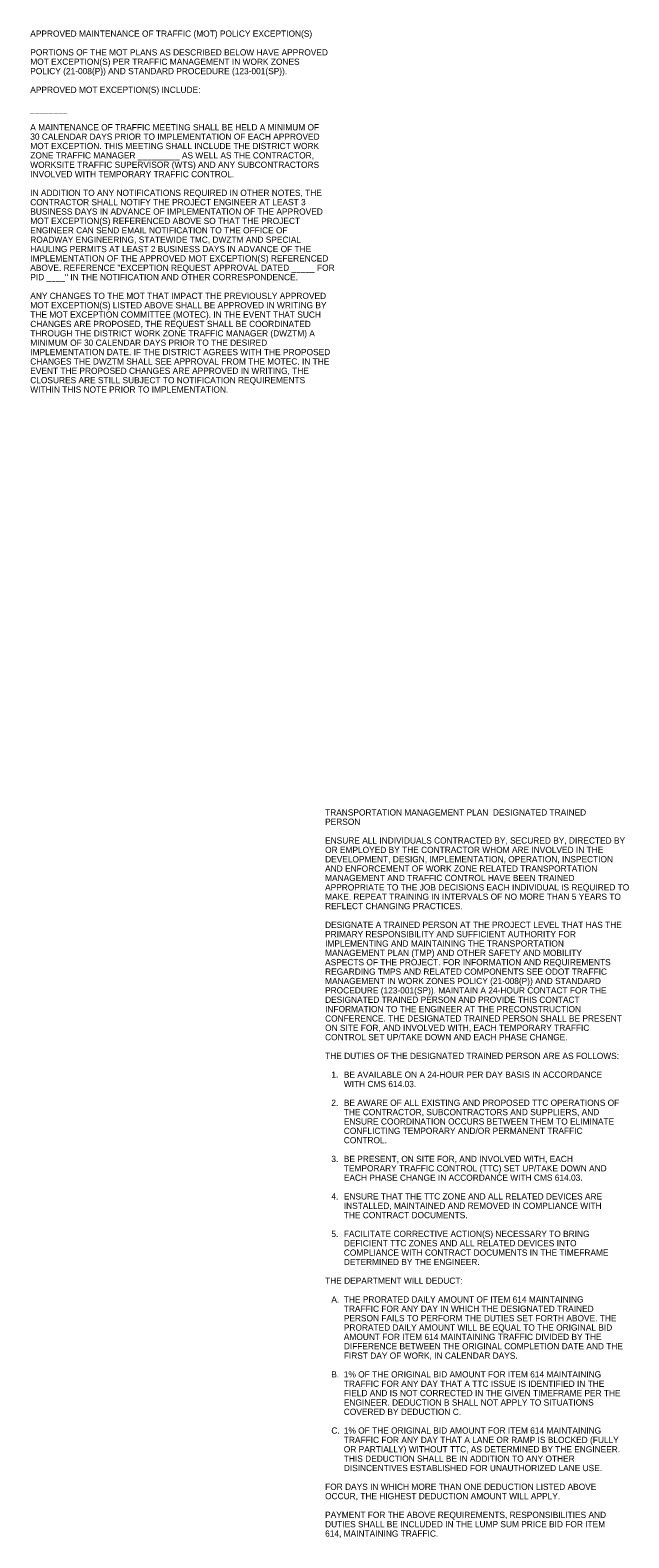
# Model space of a CAD drawing. Extents: x -65.5 to 34, y -24.3 to 23.1.
# Drawn here: x -21.45 to -8.02, y -15.72 to 18.08 of the extents above; entities that cross this region are included whole.
import ezdxf

# ---------------------------------------------------------------- set-up
doc = ezdxf.new("R2010")
doc.units = 0
doc.layers.add('SH_Text', color=7, linetype='Continuous')

msp = doc.modelspace()

# ---------------------------------------------------------------- texts
at = {"layer": 'SH_Text'}
for s, p in [('APPROVED MAINTENANCE OF TRAFFIC (MOT) POLICY EXCEPTION(S)', (-21.449, 17.935)), ('PORTIONS OF THE MOT PLANS AS DESCRIBED BELOW HAVE APPROVED ', (-21.449, 17.515)), ('MOT EXCEPTION(S) PER TRAFFIC MANAGEMENT IN WORK ZONES ', (-21.449, 17.305)), ('POLICY (21-008(P)) AND STANDARD PROCEDURE (123-001(SP)).', (-21.449, 17.095)), ('APPROVED MOT EXCEPTION(S) INCLUDE:', (-21.449, 16.675)), ('________', (-21.449, 16.255)), ('A MAINTENANCE OF TRAFFIC MEETING SHALL BE HELD A MINIMUM OF ', (-21.449, 15.835)), ('30 CALENDAR DAYS PRIOR TO IMPLEMENTATION OF EACH APPROVED ', (-21.449, 15.625)), ('MOT EXCEPTION. THIS MEETING SHALL INCLUDE THE DISTRICT WORK ', (-21.449, 15.415)), ('ZONE TRAFFIC MANAGER _________ AS WELL AS THE CONTRACTOR, ', (-21.449, 15.205)), ('WORKSITE TRAFFIC SUPERVISOR (WTS) AND ANY SUBCONTRACTORS ', (-21.449, 14.995)), ('INVOLVED WITH TEMPORARY TRAFFIC CONTROL.', (-21.449, 14.785)), ('CONTRACTOR SHALL NOTIFY THE PROJECT ENGINEER AT LEAST 3 ', (-21.449, 14.155)), ('IN ADDITION TO ANY NOTIFICATIONS REQUIRED IN OTHER NOTES, THE ', (-21.449, 14.365)), ('BUSINESS DAYS IN ADVANCE OF IMPLEMENTATION OF THE APPROVED ', (-21.449, 13.945)), ('MOT EXCEPTION(S) REFERENCED ABOVE SO THAT THE PROJECT ', (-21.449, 13.735)), ('ENGINEER CAN SEND EMAIL NOTIFICATION TO THE OFFICE OF ', (-21.449, 13.525)), ('ROADWAY ENGINEERING, STATEWIDE TMC, DWZTM AND SPECIAL ', (-21.449, 13.315)), ('HAULING PERMITS AT LEAST 2 BUSINESS DAYS IN ADVANCE OF THE ', (-21.449, 13.105)), ('IMPLEMENTATION OF THE APPROVED MOT EXCEPTION(S) REFERENCED ', (-21.449, 12.895)), ('ABOVE. REFERENCE "EXCEPTION REQUEST APPROVAL DATED _____ FOR ', (-21.449, 12.685)), ('PID ____" IN THE NOTIFICATION AND OTHER CORRESPONDENCE.', (-21.449, 12.475)), ('ANY CHANGES TO THE MOT THAT IMPACT THE PREVIOUSLY APPROVED ', (-21.449, 12.055)), ('MOT EXCEPTION(S) LISTED ABOVE SHALL BE APPROVED IN WRITING BY ', (-21.449, 11.845)), ('THE MOT EXCEPTION COMMITTEE (MOTEC). IN THE EVENT THAT SUCH ', (-21.449, 11.635)), ('CHANGES ARE PROPOSED, THE REQUEST SHALL BE COORDINATED ', (-21.449, 11.425)), ('THROUGH THE DISTRICT WORK ZONE TRAFFIC MANAGER (DWZTM) A ', (-21.449, 11.215)), ('MINIMUM OF 30 CALENDAR DAYS PRIOR TO THE DESIRED ', (-21.449, 11.005)), ('IMPLEMENTATION DATE. IF THE DISTRICT AGREES WITH THE PROPOSED ', (-21.449, 10.795)), ('CHANGES THE DWZTM SHALL SEE APPROVAL FROM THE MOTEC. IN THE ', (-21.449, 10.585)), ('EVENT THE PROPOSED CHANGES ARE APPROVED IN WRITING, THE ', (-21.449, 10.375)), ('CLOSURES ARE STILL SUBJECT TO NOTIFICATION REQUIREMENTS ', (-21.449, 10.165)), ('WITHIN THIS NOTE PRIOR TO IMPLEMENTATION.', (-21.449, 9.955)), ('TRANSPORTATION MANAGEMENT PLAN  DESIGNATED TRAINED ', (-14.834, 0.473)), ('PERSON', (-14.834, 0.263)), ('OR EMPLOYED BY THE CONTRACTOR WHOM ARE INVOLVED IN THE ', (-14.834, -0.367)), ('ENSURE ALL INDIVIDUALS CONTRACTED BY, SECURED BY, DIRECTED BY ', (-14.834, -0.157)), ('AND ENFORCEMENT OF WORK ZONE RELATED TRANSPORTATION ', (-14.834, -0.787)), ('DEVELOPMENT, DESIGN, IMPLEMENTATION, OPERATION, INSPECTION ', (-14.834, -0.577)), ('MANAGEMENT AND TRAFFIC CONTROL HAVE BEEN TRAINED ', (-14.834, -0.997)), ('APPROPRIATE TO THE JOB DECISIONS EACH INDIVIDUAL IS REQUIRED TO ', (-14.834, -1.207)), ('MAKE. REPEAT TRAINING IN INTERVALS OF NO MORE THAN 5 YEARS TO ', (-14.834, -1.417)), ('REFLECT CHANGING PRACTICES.', (-14.834, -1.627)), ('DESIGNATE A TRAINED PERSON AT THE PROJECT LEVEL THAT HAS THE ', (-14.834, -2.047)), ('PRIMARY RESPONSIBILITY AND SUFFICIENT AUTHORITY FOR ', (-14.834, -2.257)), ('IMPLEMENTING AND MAINTAINING THE TRANSPORTATION ', (-14.834, -2.467)), ('MANAGEMENT PLAN (TMP) AND OTHER SAFETY AND MOBILITY ', (-14.834, -2.677)), ('ASPECTS OF THE PROJECT. FOR INFORMATION AND REQUIREMENTS ', (-14.834, -2.887)), ('REGARDING TMPS AND RELATED COMPONENTS SEE ODOT TRAFFIC ', (-14.834, -3.097)), ('MANAGEMENT IN WORK ZONES POLICY (21-008(P)) AND STANDARD ', (-14.834, -3.307)), ('PROCEDURE (123-001(SP)). MAINTAIN A 24-HOUR CONTACT FOR THE ', (-14.834, -3.517)), ('DESIGNATED TRAINED PERSON AND PROVIDE THIS CONTACT ', (-14.834, -3.727)), ('CONFERENCE. THE DESIGNATED TRAINED PERSON SHALL BE PRESENT ', (-14.834, -4.147)), ('INFORMATION TO THE ENGINEER AT THE PRECONSTRUCTION ', (-14.834, -3.937)), ('ON SITE FOR, AND INVOLVED WITH, EACH TEMPORARY TRAFFIC ', (-14.834, -4.357)), ('CONTROL SET UP/TAKE DOWN AND EACH PHASE CHANGE.', (-14.834, -4.567)), ('THE DUTIES OF THE DESIGNATED TRAINED PERSON ARE AS FOLLOWS:', (-14.834, -4.987)), ('1.', (-14.694, -5.407)), ('BE AVAILABLE ON A 24-HOUR PER DAY BASIS IN ACCORDANCE ', (-14.414, -5.407)), ('WITH CMS 614.03.', (-14.414, -5.617)), ('2.', (-14.694, -6.037)), ('BE AWARE OF ALL EXISTING AND PROPOSED TTC OPERATIONS OF ', (-14.414, -6.037)), ('THE CONTRACTOR, SUBCONTRACTORS AND SUPPLIERS, AND ', (-14.414, -6.247)), ('ENSURE COORDINATION OCCURS BETWEEN THEM TO ELIMINATE ', (-14.414, -6.457)), ('CONFLICTING TEMPORARY AND/OR PERMANENT TRAFFIC ', (-14.414, -6.667)), ('CONTROL.', (-14.414, -6.877)), ('3.', (-14.694, -7.297)), ('TEMPORARY TRAFFIC CONTROL (TTC) SET UP/TAKE DOWN AND ', (-14.414, -7.507)), ('BE PRESENT, ON SITE FOR, AND INVOLVED WITH, EACH ', (-14.414, -7.297)), ('EACH PHASE CHANGE IN ACCORDANCE WITH CMS 614.03.', (-14.414, -7.717)), ('4.', (-14.694, -8.137)), ('ENSURE THAT THE TTC ZONE AND ALL RELATED DEVICES ARE ', (-14.414, -8.137)), ('THE CONTRACT DOCUMENTS.', (-14.414, -8.557)), ('INSTALLED, MAINTAINED AND REMOVED IN COMPLIANCE WITH ', (-14.414, -8.347)), ('5.', (-14.694, -8.977)), ('FACILITATE CORRECTIVE ACTION(S) NECESSARY TO BRING ', (-14.414, -8.977)), ('DEFICIENT TTC ZONES AND ALL RELATED DEVICES INTO ', (-14.414, -9.187)), ('COMPLIANCE WITH CONTRACT DOCUMENTS IN THE TIMEFRAME ', (-14.414, -9.397)), ('DETERMINED BY THE ENGINEER.', (-14.414, -9.607)), ('THE DEPARTMENT WILL DEDUCT:', (-14.834, -10.027)), ('A.', (-14.694, -10.447)), ('THE PRORATED DAILY AMOUNT OF ITEM 614 MAINTAINING ', (-14.414, -10.447)), ('TRAFFIC FOR ANY DAY IN WHICH THE DESIGNATED TRAINED ', (-14.414, -10.657)), ('PERSON FAILS TO PERFORM THE DUTIES SET FORTH ABOVE. THE ', (-14.414, -10.867)), ('AMOUNT FOR ITEM 614 MAINTAINING TRAFFIC DIVIDED BY THE ', (-14.414, -11.287)), ('PRORATED DAILY AMOUNT WILL BE EQUAL TO THE ORIGINAL BID ', (-14.414, -11.077)), ('DIFFERENCE BETWEEN THE ORIGINAL COMPLETION DATE AND THE ', (-14.414, -11.497)), ('FIRST DAY OF WORK, IN CALENDAR DAYS.', (-14.414, -11.707)), ('B.', (-14.694, -12.127)), ('1% OF THE ORIGINAL BID AMOUNT FOR ITEM 614 MAINTAINING ', (-14.414, -12.127)), ('TRAFFIC FOR ANY DAY THAT A TTC ISSUE IS IDENTIFIED IN THE ', (-14.414, -12.337)), ('FIELD AND IS NOT CORRECTED IN THE GIVEN TIMEFRAME PER THE ', (-14.414, -12.547)), ('COVERED BY DEDUCTION C.', (-14.414, -12.967)), ('ENGINEER. DEDUCTION B SHALL NOT APPLY TO SITUATIONS ', (-14.414, -12.757)), ('C.', (-14.694, -13.387)), ('TRAFFIC FOR ANY DAY THAT A LANE OR RAMP IS BLOCKED (FULLY ', (-14.414, -13.597)), ('1% OF THE ORIGINAL BID AMOUNT FOR ITEM 614 MAINTAINING ', (-14.414, -13.387)), ('OR PARTIALLY) WITHOUT TTC, AS DETERMINED BY THE ENGINEER. ', (-14.414, -13.807)), ('THIS DEDUCTION SHALL BE IN ADDITION TO ANY OTHER ', (-14.414, -14.017)), ('DISINCENTIVES ESTABLISHED FOR UNAUTHORIZED LANE USE.', (-14.414, -14.227)), ('FOR DAYS IN WHICH MORE THAN ONE DEDUCTION LISTED ABOVE ', (-14.834, -14.647)), ('OCCUR, THE HIGHEST DEDUCTION AMOUNT WILL APPLY.', (-14.834, -14.857)), ('PAYMENT FOR THE ABOVE REQUIREMENTS, RESPONSIBILITIES AND ', (-14.834, -15.277)), ('DUTIES SHALL BE INCLUDED IN THE LUMP SUM PRICE BID FOR ITEM ', (-14.834, -15.487)), ('614, MAINTAINING TRAFFIC.', (-14.834, -15.697))]:
    msp.add_text(s, height=0.14, dxfattribs=at).set_placement(p)

doc.saveas('drawing.dxf')
